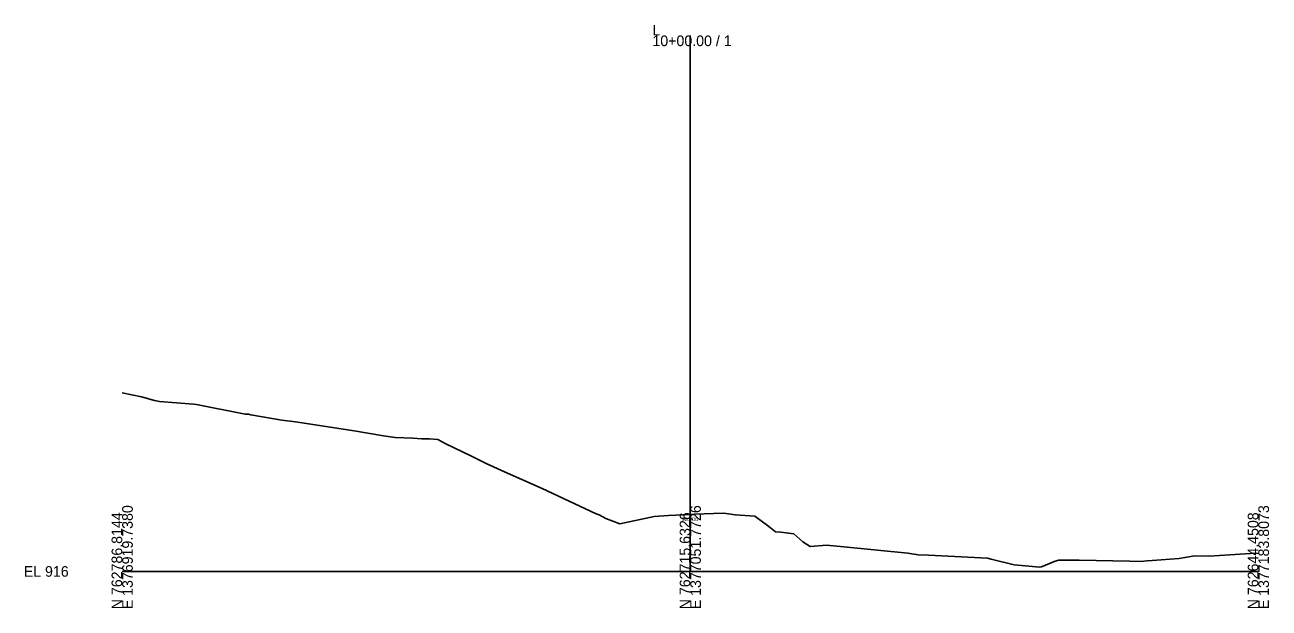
# Model space of a CAD drawing. Extents: x -26 to 303, y -10 to 6523.
# Drawn here: x -25.7 to 302.8, y -9.7 to 144.3 of the extents above; entities that cross this region are included whole.
import ezdxf

# ---------------------------------------------------------------- set-up
doc = ezdxf.new("R2010")
doc.units = 0
for name, color, linetype in [('Exist Cross Section Cell', 7, 'Continuous'), ('Exist XS Center Line Elevation Label', 7, 'Continuous'), ('Exist XS Ground Line', 7, 'Continuous')]:
    doc.layers.add(name, color=color, linetype=linetype)

msp = doc.modelspace()

# ---------------------------------------------------------------- linework, layer by layer
at = {"layer": 'Exist Cross Section Cell'}
for p, q in [((150, 0), (150, 141.53)), ((0, 0), (150, 0)), ((150, 0), (300, 0))]:
    msp.add_line(p, q, dxfattribs=at)
at = {"layer": 'Exist XS Ground Line'}
for p, q in [((0, 47.18), (5.12, 46.14)), ((5.12, 46.14), (8.56, 45.17)), ((8.56, 45.17), (9.85, 44.87)), ((9.85, 44.87), (18.8, 44.2)), ((18.8, 44.2), (19.61, 44.08)), ((19.61, 44.08), (32.48, 41.56)), ((32.48, 41.56), (32.84, 41.52)), ((32.84, 41.52), (33.36, 41.5)), ((33.36, 41.5), (33.96, 41.35)), ((33.96, 41.35), (42.17, 39.96)), ((42.17, 39.96), (45.73, 39.48)), ((45.73, 39.48), (61.22, 37.14)), ((61.22, 37.14), (68.98, 35.77)), ((68.98, 35.77), (70.23, 35.65)), ((70.23, 35.65), (72.05, 35.4)), ((72.05, 35.4), (76.73, 35.23)), ((76.73, 35.23), (79.14, 35.02)), ((79.14, 35.02), (81.18, 34.98)), ((81.18, 34.98), (83.32, 34.81)), ((83.32, 34.81), (85.3, 33.82)), ((85.3, 33.82), (92.25, 30.42)), ((92.25, 30.42), (96.07, 28.51)), ((96.07, 28.51), (100.93, 26.33)), ((100.93, 26.33), (110.93, 21.88)), ((110.93, 21.88), (125.17, 15.25)), ((125.17, 15.25), (125.9, 14.94)), ((125.9, 14.94), (127.66, 14)), ((127.66, 14), (131.4, 12.59)), ((131.4, 12.59), (140.46, 14.54)), ((140.46, 14.54), (144.23, 14.74)), ((144.23, 14.74), (150, 15.06)), ((150, 15.06), (151.15, 15.1)), ((151.15, 15.1), (158.67, 15.39)), ((158.67, 15.39), (159.45, 15.3)), ((159.45, 15.3), (161.82, 14.96)), ((161.82, 14.96), (167.03, 14.59)), ((167.03, 14.59), (170.71, 11.86)), ((170.71, 11.86), (172.54, 10.42)), ((172.54, 10.42), (173.92, 10.35)), ((173.92, 10.35), (177.32, 9.92)), ((177.32, 9.92), (179.75, 7.79)), ((179.75, 7.79), (181.64, 6.62)), ((181.64, 6.62), (186.01, 6.91)), ((186.01, 6.91), (190.56, 6.5)), ((190.56, 6.5), (207.45, 4.78)), ((207.45, 4.78), (210.18, 4.37)), ((210.18, 4.37), (212.89, 4.25)), ((212.89, 4.25), (228.48, 3.52)), ((228.48, 3.52), (229.48, 3.24)), ((271.98, 2.91), (279.09, 3.45)), ((279.09, 3.45), (283.17, 4.11)), ((283.17, 4.11), (286.98, 4.01)), ((286.98, 4.01), (297.93, 4.71)), ((297.93, 4.71), (300, 4.84)), ((229.48, 3.24), (235.49, 1.73)), ((235.49, 1.73), (242.28, 1.16)), ((242.28, 1.16), (242.7, 1.24)), ((242.7, 1.24), (246.35, 2.72)), ((246.35, 2.72), (247.28, 2.98)), ((247.28, 2.98), (251.15, 2.95)), ((251.15, 2.95), (252.72, 2.94)), ((252.72, 2.94), (266.02, 2.68)), ((266.02, 2.68), (268.92, 2.65)), ((268.92, 2.65), (270.66, 2.76)), ((270.66, 2.76), (271.98, 2.91))]:
    msp.add_line(p, q, dxfattribs=at)

# ---------------------------------------------------------------- texts
at = {"layer": 'Exist Cross Section Cell'}
for s, p in [('10+00.00 / 1', (140, 138.73)), ('L', (140, 141.53)), ('EL 916', (-26, -1.4))]:
    msp.add_text(s, height=2.8, dxfattribs=at).set_placement(p)
for s, p in [('E 1376919.7380', (2.8, -10)), ('E 1377051.7726', (152.8, -10)), ('E 1377183.8073', (302.8, -10)), ('N 762786.8144', (0, -10)), ('N 762715.6326', (150, -10)), ('N 762644.4508', (300, -10))]:
    msp.add_text(s, height=2.8, rotation=90, dxfattribs=at).set_placement(p)
at = {"layer": 'Exist XS Center Line Elevation Label'}
msp.add_text('931.06', height=0.998, dxfattribs=at).set_placement((147.79, 13.29))

doc.saveas('drawing.dxf')
